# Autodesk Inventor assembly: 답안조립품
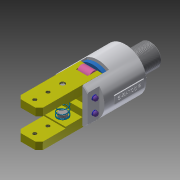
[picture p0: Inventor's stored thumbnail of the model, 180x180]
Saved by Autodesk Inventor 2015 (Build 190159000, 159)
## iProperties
Created: 2019-02
Part Number: 답안조립품
Document SubType Name: Assembly
Designer: now
Author: now
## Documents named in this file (11)
- C:\Users\now\Desktop\490207V1016\답안조립품.iam
- C:\Users\now\Desktop\490207V1016\E-링.ipt
- C:\Users\now\Desktop\490207V1016\O-링.ipt
- C:\Users\now\Desktop\490207V1016\가이드핀.ipt
- C:\Users\now\Desktop\490207V1016\본체.ipt
- C:\Users\now\Desktop\490207V1016\부시.ipt
- C:\Users\now\Desktop\490207V1016\스프링.ipt
- C:\Users\now\Desktop\490207V1016\평행핀 6x28.ipt
- C:\Users\now\Desktop\490207V1016\피스톤.ipt
- C:\Users\now\Desktop\490207V1016\핀.ipt
- C:\Users\now\Desktop\490207V1016\핑거.ipt
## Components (13 placed, 6 different names)
1. E-링:1
2. O-링:1
3. 가이드핀:1
4. 피스톤:1
5. 핀:1
6. 핑거:1
7. O-링:2
8. 핑거:2
9. 핀:2
10. E-링:2
11. E-링:3
12. E-링:4
13. 가이드핀:2
